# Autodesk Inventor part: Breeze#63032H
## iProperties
Company: Franklin Manufacturing Inc.
Shininess: 64.0
Length Units: 11272
Angle Units: 11279
Time Units: 11290
Mass Units: 11286
Length Display Precision: 3
Angle Display Precision: 2
Compacted: True
Part Number: Breeze#63032H
Document SubType Name: Modeling
Created: 2004-02
Designer: KArthur
Material: Stainless Steel, 304
Cost Center: 0.1 lbmass
Authority: 0.27 in^3
Manufacturer: Standard
Standards Organization: Custom
Description: Stainless Worm Drive Hose Clamp, Ø2
Density: 0.0
Volumn: 0.0
Area: 0.0
PropertySet Name: Model Information
Control State: 0
Master: False
Checked Out: False
Cutlength: 0
TotalMass: 0.1 lbmass
TotalVolume: 0.27 in^3
Author: KArthur
Title: Stainless Hose Clamp, Breeze #63032H
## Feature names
1. Nut [Extrusion]
2. Band [Extrusion]
3. Band Extension [Extrusion]
4. Fillet1
5. Extrusion1
6. Extrusion2
7. Extrusion3
8. Extrusion4
9. Drive Groove [Extrusion]
10. Drive Groove Pattern [Circular Pattern]
